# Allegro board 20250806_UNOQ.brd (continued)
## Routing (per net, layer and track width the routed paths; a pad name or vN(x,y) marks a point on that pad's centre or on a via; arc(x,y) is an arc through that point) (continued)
VBAT: length 0.4
  TOP w0.203: R603.2 45.73,16.34 45.73,16.05
  vias: v1(45.72,15.72) v1(45.72,15.46) v1(45.73,15.23) v1(45.97,15.72) v1(45.97,15.46) v1(45.98,15.23) v1(46.19,15.71) v1(46.18,15.46) v1(46.19,15.24) v1(46.43,15.71) v1(46.42,15.46) v1(46.43,15.24) v2(45.72,15.72) v2(45.72,15.46) v2(45.73,15.23) v2(45.97,15.72) v2(45.97,15.46) v2(45.98,15.23) v2(46.19,15.71) v2(46.18,15.46) v2(46.19,15.24) v2(46.43,15.71) v2(46.42,15.46) v2(46.43,15.24) v3(6.49,40.57) v3(6.49,40.12) v3(6.89,40.56) v3(6.89,40.11) v3(7.29,40.56) v3(7.29,40.11) v3(13.89,7.37) v3(14.17,7.06) v3(14.43,6.68) v3(14.86,6.68) v3(15.32,6.68) v3(15.57,7.14) v3(45.85,14.96) v3(46.22,14.96) v3(46.59,14.96) v3(46.74,15.66) v3(46.74,15.3) v3(46.94,14.99) v4(7.62,40.3) v4(7.62,40.04) v4(7.62,39.79) v4(7.87,40.3) v4(7.87,40.04) v4(7.87,39.79) v4(8.13,40.3) v4(8.13,40.04) v4(8.13,39.79) v4(14.4,7.54) v4(14.43,7.26) v4(14.58,7.01) v4(14.68,7.52) v4(14.68,7.26) v4(14.81,7.01) v4(14.94,7.52) v4(14.94,7.26) v4(15.04,7.01) v4(15.19,7.52) v4(15.19,7.26) v4(15.29,7.01) v5(7.4,14.04) v5(7.4,13.81) v5(7.4,13.56) v5(7.62,40.3) v5(7.62,40.04) v5(7.62,39.79) v5(7.62,14.04) v5(7.62,13.81) v5(7.62,13.56) v5(7.87,40.3) v5(7.87,40.04) v5(7.87,39.79) v5(7.85,14.04) v5(7.85,13.81) v5(7.85,13.56) v5(8.13,40.3) v5(8.13,40.04) v5(8.13,39.79) v5(8.11,14.04) v5(8.11,13.81) v5(8.11,13.56)
VBAT_CONN_VSNS_P: length 7.3
  S3 w0.064: v2(46.29,16.4) 46.29,16.47 46.36,16.54 46.53,16.54 46.61,16.46 46.61,16.23 46.52,16.14 45.11,16.14 43.82,14.85 v2(40.51,14.85)
VBUS_DIV8: length 4
  TOP w0.254: R3019.2 R3020.1 33.22,51.38 v2(33.06,51.55)
  G2 w0.203: v2(34.77,52.2) 34.82,52.25 34.92,52.25 v1(34.98,52.3)
  S3 w0.203: v3(32.94,51.16) 32.94,51.44 v2(33.06,51.55) ; v3(34.62,51.94) 34.62,52.04 v2(34.77,52.2)
  S6 w0.254: v3(32.94,51.16) 33.73,51.94 v3(34.62,51.94)
VBUS_POWER_SWITCH_DISABLE_N: length 47.9
  TOP w0.066: v2(44.34,50.31) 44.54,50.51 44.54,54.41 43.79,55.16 JCTL1.10
  S3 w0.064: v2(44.34,50.31) 44.34,48.12 v3(43.48,47.26) ; v3(19.97,37.5) 19.88,37.41 18.3,37.41 17.76,37.95 15.06,37.95 v3(13.8,39.21)
  S6 w0.064: v3(43.48,47.26) 43.48,47.21 41.58,45.31 41.58,44.95 39.29,42.66 37.46,42.66 36.58,41.78 34.65,41.78 33.25,40.39 22.15,40.39 19.97,38.21 v3(19.97,37.5) ; v3(13.8,39.21) 13.9,39.21 v4(14.05,39.07)
  G7 w0.064: v4(14.05,39.07) 13.61,38.63 12.79,38.63 v5(12.23,39.19)
AMUX_1_TP: length 6.5
  S3 w0.064: v2(39.66,8.85) 39.66,9.84 40.09,10.27 40.09,13.52 39.64,13.97 39.64,14.33 39.24,14.73 v2(39.24,14.81)
ANT_CH0: length 5.6
  TOP w0.066: U2901.2 19.36,62.95 18.89,63.42 15.88,63.42 15.71,63.59 ANT1.1
AUX_CTRL_1: length 13.1
  TOP w0.066: R3003.1 34.93,58.64 34.61,58.96 v2(34.2,58.96) ; U3001.G1 34.32,51.54 33.83,51.05 v2(33.83,50.23) R3001.1
  S3 w0.064: v2(33.83,50.23) 33.83,50.24 33.32,50.75 33.32,51.78 32.55,52.56 32.55,55.32 33.4,56.18 33.4,57.58 33.84,58.02 33.84,58.61 v2(34.2,58.96)
AUX_CTRL_2: length 15.6
  TOP w0.066: U3001.H1 34.57,50.86 34.54,50.83 R3002.1 34.52,49.86 v2(34.14,50.24) ; 36.79,57.5 36.79,57.03 36.49,56.74 35.08,56.74 34.37,57.45 34.37,58.16 v2(34.09,58.44)
  S3 w0.064: v2(34.09,58.44) 34.09,58.03 33.53,57.48 33.53,56.09 32.72,55.28 32.72,52.71 33.5,51.93 33.5,50.88 v2(34.14,50.24)
BAT_ID: length 8
  S3 w0.064: v2(38.89,8.86) 38.89,9.05 38.74,9.19 38.75,9.2 38.75,9.8 v2(38.93,9.99) 39.55,9.99 39.95,10.39 39.95,13.48 39.48,13.95 39.48,14.33 39.18,14.63 39.12,14.63 38.69,15.06 v2(38.69,15.41)
BAT_THERM: length 6.8
  S3 w0.064: v2(39.26,14.28) 39.26,13.97 39.8,13.43 39.8,10.52 39.52,10.24 38.74,10.24 v2(38.5,10) 38.63,9.87 38.63,9.25 38.4,9.02 v2(38.4,8.85)
BOOT_CAP: length 5.1
  TOP w0.15: v1(40.95,14.28) 40.96,14.27 41.36,14.27 41.65,13.98 43.32,13.98 v1(43.36,14.01)
  G2 w0.2: v1(40.95,14.28) 40.97,14.3 41.36,14.3 41.65,14.01 v1(43.36,14.01)
BOOT_CONFIG0: length 2.7
  TOP w0.066: SOC1.AH9 22.97,36.88 R1304.1 R1303.2
BOOT_CONFIG1: length 2.4
  TOP w0.066: SOC1.AJ7 23.73,38.12 22.88,38.12 R1306.1 R1305.2
BOOT_CONFIG2: length 2.9
  TOP w0.066: R1307.2 R1308.1 22.88,37.55 23.37,37.55 23.89,37.03 24.32,37.03 SOC1.AH8
BOOT_CONFIG3: length 2.9
  TOP w0.066: SOC1.AH6 24.1,38.08 23.5,38.68 22.86,38.68 R1310.1 R1309.2
CBLPWR_N: length 5.4
  TOP w0.066: PMIC1.T10 36.65,14.56 v2(36.65,14.55)
  S3 w0.064: v2(36.65,14.55) 36.65,14.18 36.25,13.78 36.25,12.34 36.1,12.19 36.1,11.4 36.19,11.31 36.19,10.45 36.2,10.44 36.33,10.3 36.56,10.3 v2(36.93,9.93)
CC_OUT: length 4.2
  S3 w0.064: v2(35.28,21.95) 35.74,21.95 35.84,21.84 35.84,18.45 35.86,18.43 v2(35.86,18.24)
CCI_I2C_SCL0: length 29.7
  S3 w0.064: v2(26.17,38.48) 25.62,37.93 19.91,37.93 19.57,37.59 18.4,37.59 17.85,38.14 16.53,38.14 12.68,41.99 12.68,48.01 13.76,49.09 13.76,51.18 13.96,51.38 v3(13.96,52.83)
  S6 w0.064: v5(15.7,53.05) 14.18,53.05 v3(13.96,52.83)
  BOTTOM w0.066: v5(15.7,53.05) 15.35,53.4 R2607.1
CCI_I2C_SCL0_CONN: length 2.5
  BOTTOM w0.066: JMEDIA1.51 13.34,54.17 13.79,53.72 D26051.2 R2607.2
CCI_I2C_SCL1: length 47.6
  S3 w0.064: v2(26.97,39.68) 26.97,39.8 25.7,41.07 22.86,41.07 20.75,43.18 18.85,43.18 16.38,45.65 16.38,51.28 14.4,53.26 14.4,58.43 v3(14.05,58.79)
  S6 w0.064: v3(14.05,58.79) 14.05,58.75 14.32,58.48 14.32,57.62 14.62,57.31 26.03,57.31 26.57,57.86 26.57,59.75 28.57,61.74 v5(29.06,61.74)
  BOTTOM w0.066: v5(29.06,61.74) 29.06,61.76 29.31,62 R2610.1 30.19,62 R2611.1
CCI_I2C_SCL1_CONN: length 3.3
  BOTTOM w0.066: R2611.2 30.77,61.93 D26049.2 30.77,60.66 31.11,60.31 JMEDIA1.24
CCI_I2C_SDA0: length 27.8
  S3 w0.064: v3(14.36,52.48) 14.18,52.3 14.18,51.34 13.96,51.12 13.96,49.02 12.84,47.9 12.84,42.13 16.64,38.33 17.93,38.33 18.52,37.74 19.47,37.74 19.83,38.1 25.62,38.1 25.94,38.42 25.94,38.65 v2(26.17,38.88)
  S6 w0.064: v3(14.36,52.48) 14.4,52.48 v5(14.76,52.83)
  BOTTOM w0.066: R2608.1 14.75,52.84 v5(14.76,52.83)
CCI_I2C_SDA0_CONN: length 3.3
  BOTTOM w0.066: R2608.2 12.92,52.84 12.51,53.25 D26050.2 12.51,53.86 12.06,54.3 12.06,54.95
CCI_I2C_SDA1: length 49.7
  S3 w0.064: v3(14,58.36) 14.22,58.13 14.22,53.19 16.21,51.21 16.21,45.57 18.75,43.03 19.75,43.03 19.76,43.02 20.71,43.02 22.83,40.89 25.65,40.89 26.77,39.78 26.77,39.09 v2(26.57,38.88)
  S6 w0.064: v3(14,58.36) 14.16,58.19 14.16,57.55 14.54,57.17 26.12,57.17 26.7,57.75 26.7,59.67 28.48,61.45 v5(28.7,61.45)
  BOTTOM w0.066: v5(28.7,61.45) 28.7,61.73 28.94,61.97 29.06,61.97 29.48,62.39 30.62,62.39 30.77,62.54 R2609.1 31.08,62.74 R2612.1
CCI_I2C_SDA1_CONN: length 3.6
  BOTTOM w0.066: 32.38,58.85 32.38,59.47 31.32,60.53 D26048.2 R2612.2
CDC_CP_FLY_N: length 2
  TOP w0.2: C501.2 42.19,19.59 41.52,18.91 PMIC1.A27 PMIC1.B26
CDC_CP_FLY_P: length 2.3
  TOP w0.2: C501.1 42.24,20.09 PMIC1.A25
CDC_CP_VNEG: length 2.9
  TOP w0.2: F501.1 43.95,19.25 C502.1 43.18,19.25 42.61,18.68 42.16,18.68 41.73,18.24 PMIC1.C27
CDC_PA_VNEG: length 4.7
  TOP w0.16: 41.23,17.4 40.82,17.4 40.67,17.25 PMIC1.K24 ; C503.1 42.49,18.23 41.65,17.39 PMIC1.F26
  TOP w0.2: 41.23,17.4 PMIC1.F26 ; F501.2 43.91,18.23 C503.1
CSI0_A0_CLK_M: length 25.4
  TOP w0.058: v2(30.66,39.69) 30.65,39.68 SOC1.N2
  S3 w0.053: v3(27.76,43.54) 27.58,43.36 27.58,42.95 28.12,42.42 29.6,42.42 30.8,41.22 30.8,40.37 30.9,40.27 30.9,39.93 v2(30.66,39.69)
  S6 w0.053: v3(27.76,43.54) 27.76,43.77 v5(27.69,43.85)
  BOTTOM w0.058: JMEDIA1.33 24.26,54.95 24.2,54.89 24.2,53.97 24.3,53.88 25.14,53.88 25.32,53.69 25.32,53.31 U2610.7 U2610.4 25.35,52.08 25.35,51.57 27.59,49.33 27.59,48.83 27.45,48.7 26.9,48.7 26.84,48.64 26.84,48.52 26.9,48.46 27.45,48.46 27.59,48.32 27.59,48.1 27.45,47.96 26.9,47.96 26.84,47.9 26.84,47.78 26.9,47.73 27.45,47.73 27.59,47.59 27.59,47.36 27.45,47.22 26.9,47.22 26.84,47.16 26.84,47.05 26.9,46.99 27.45,46.99 27.59,46.85 27.59,46.62 27.45,46.49 26.9,46.49 26.84,46.43 26.84,46.31 26.9,46.25 27.45,46.25 27.59,46.12 27.59,44.18 27.69,44.08 v5(27.69,43.85)
CSI0_A1_LN1_P: length 25.2
  TOP w0.058: 30.17,39.68 30.2,39.68 v2(30.27,39.61)
  S3 w0.05: 30.29,39.65 30.28,39.63
  S3 w0.053: v3(26.32,43.85) 26.5,43.67 26.5,43.47 27.94,42.04 29.39,42.04 30.31,41.11 30.31,39.74 30.29,39.72 30.29,39.65
  S3 w0.058: 30.28,39.63 30.27,39.62 v2(30.27,39.61)
  S6 w0.053: v5(26.39,44.13) 26.34,44.13 26.32,44.11 v3(26.32,43.85) ; v5(26.61,52.17) 26.72,52.07 26.72,51.7 26.66,51.65 26.24,51.65 26.19,51.7 26.19,51.79 26.14,51.84 26.03,51.84 25.98,51.79 25.98,51.7 25.92,51.65 25.82,51.65 25.76,51.7 25.76,51.79 25.71,51.84 25.6,51.84 25.55,51.79 25.55,51.7 25.5,51.65 25.17,51.65 24.99,51.47 24.99,50.94 v5(24.88,50.83)
  BOTTOM w0.058: v5(26.39,44.13) 26.48,44.22 26.48,45.18 24.98,46.68 24.98,47.24 24.92,47.3 24.58,47.3 24.44,47.43 24.44,47.66 24.58,47.8 24.92,47.8 24.98,47.86 24.98,47.97 24.92,48.03 24.58,48.03 24.44,48.17 24.44,48.4 24.58,48.53 24.92,48.53 24.98,48.59 24.98,48.71 24.92,48.77 24.58,48.77 24.44,48.91 24.44,49.13 24.58,49.27 24.92,49.27 24.98,49.33 24.98,50.73 v5(24.88,50.83) ; v5(26.61,52.17) 26.58,52.17 U2610.2 U2610.9 26.69,53.29 26.69,53.68 26.88,53.87 27.81,53.87 27.87,53.93 27.87,54.89 27.81,54.95 27.3,54.95
CSI0_A2_LN2_M: length 25.1
  S3 w0.05: 29.78,39.83 v2(29.78,39.68)
  S3 w0.053: 29.78,39.83 29.71,39.9 29.71,39.9 29.6,40.01 29.6,40.18 29.7,40.27 29.7,40.3 29.7,40.3 29.7,40.9 29.11,41.49 27.59,41.49 26.37,42.71 24.9,42.71 24.2,43.41 24.2,43.81 24.19,43.82 v3(24.02,43.82)
  S6 w0.053: v5(18.12,50.42) 18.23,50.53 18.61,50.53 19.2,51.12 19.2,52.05 v5(19.39,52.24) ; v5(24.11,44.1) 24.08,44.13 24.02,44.08 v3(24.02,43.82)
  BOTTOM w0.058: v5(19.39,52.24) U2609.10 19.2,53.31 19.2,53.62 19.32,53.74 20.25,53.74 20.39,53.88 20.39,54.89 20.45,54.95 JMEDIA1.39 ; v5(18.12,50.42) 18.22,50.52 18.65,50.52 24.21,44.96 24.21,44.19 v5(24.11,44.1)
CSI0_B0_LN0_P: length 25.4
  S3 w0.05: 31.07,40.44 31.07,40.43 31.08,40.43 31.08,39.8 30.85,39.58 30.85,39.21 30.78,39.14 30.71,39.14 v2(30.57,39.28)
  S3 w0.053: v3(28.35,43.54) 28.52,43.36 28.52,43.08 29.02,42.58 29.7,42.58 31.07,41.2 31.07,40.44
  S6 w0.053: v3(28.35,43.54) 28.35,43.79 28.4,43.85 v5(28.44,43.85)
  BOTTOM w0.058: JMEDIA1.23 31.62,54.95 31.68,54.89 31.68,53.92 31.86,53.74 32.7,53.74 32.81,53.63 32.81,53.29 U2606.6 U2606.5 32.63,51.96 32.8,51.79 32.8,51.11 32.45,50.76 32.36,50.76 32.32,50.8 32.24,50.8 32.16,50.72 32.16,50.63 32.2,50.59 32.2,50.51 31.9,50.21 31.82,50.21 31.52,50.5 31.33,50.5 31.17,50.34 31.17,50.14 31.46,49.85 31.46,49.77 31.38,49.69 31.29,49.69 31,49.98 30.81,49.98 30.65,49.82 30.65,49.62 30.94,49.33 30.94,49.25 30.86,49.17 30.77,49.17 30.48,49.46 30.29,49.46 30.13,49.3 30.13,49.1 30.42,48.81 30.42,48.73 30.34,48.65 30.25,48.65 29.96,48.94 29.77,48.94 29.6,48.77 29.6,48.58 29.9,48.29 29.9,48.21 28.54,46.85 28.54,44.18 28.44,44.08 v5(28.44,43.85)
CSI0_B1_LN1_M: length 25.1
  TOP w0.058: v2(30.22,39.2) 30.17,39.25 30.17,39.28
  S3 w0.05: 30.46,39.71 30.46,39.54 30.22,39.3 v2(30.22,39.2)
  S3 w0.053: v3(26.8,43.85) 26.62,43.67 26.62,43.52 27.99,42.15 29.44,42.15 30.43,41.16 30.43,39.74 30.46,39.71
  S6 w0.053: v5(25.21,50.83) 25.11,50.93 25.11,51.42 25.22,51.53 26.71,51.53 26.83,51.65 26.83,52.07 v5(26.94,52.17) ; v5(26.71,44.13) 26.75,44.16 26.8,44.11 v3(26.8,43.85)
  BOTTOM w0.058: v5(25.21,50.83) 25.11,50.73 25.11,49.27 24.97,49.14 24.63,49.14 24.57,49.08 24.57,48.96 24.63,48.9 24.97,48.9 25.11,48.77 25.11,48.54 24.97,48.4 24.63,48.4 24.57,48.34 24.57,48.22 24.63,48.17 24.97,48.17 25.11,48.03 25.11,47.8 24.97,47.66 24.63,47.66 24.57,47.6 24.57,47.49 24.63,47.43 24.97,47.43 25.11,47.29 25.11,46.74 26.62,45.23 26.62,44.22 v5(26.71,44.13) ; v5(26.94,52.17) U2610.1 U2610.10 26.82,53.31 26.82,53.62 26.94,53.74 27.87,53.74 28.01,53.88 28.01,54.89 28.07,54.95 JMEDIA1.27
CSI0_B2_LN3_P: length 25.3
  S3 w0.05: 29.97,40.44 29.97,40.43 29.97,40.43 29.97,39.49 v2(29.77,39.28)
  S3 w0.053: v3(25.18,43.84) 25.38,43.65 25.38,43.19 25.58,43 26.48,43 27.71,41.77 29.24,41.77 29.97,41.03 29.97,40.44
  S6 w0.053: v5(25.26,44.13) 25.26,43.92 v3(25.18,43.84)
  BOTTOM w0.058: JMEDIA1.47 16.38,54.95 16.44,54.89 16.44,53.92 16.62,53.74 17.46,53.74 17.57,53.63 17.57,53.29 U2609.6 U2609.5 17.39,51.98 17.57,51.8 17.57,51.49 17.8,51.27 19.14,51.27 24.81,45.6 24.81,45.52 24.78,45.49 24.78,45.41 24.86,45.33 24.95,45.33 24.97,45.35 25.06,45.35 25.36,45.05 25.36,44.76 25.3,44.7 25.21,44.7 25.15,44.64 25.15,44.53 25.21,44.47 25.3,44.47 25.36,44.41 25.36,44.23 v5(25.26,44.13)
CSI0_C0_LN0_M: length 25.3
  S3 w0.05: 31.19,40.44 31.19,40.43 31.19,40.43 31.19,39.76 30.97,39.54 30.97,39.16 30.83,39.03 30.71,39.03 v2(30.57,38.88)
  S3 w0.053: v3(28.82,43.54) 28.81,43.54 28.64,43.37 28.64,43.13 29.07,42.7 29.74,42.7 31.19,41.25 31.19,40.44
  S6 w0.053: v3(28.82,43.54) 28.82,43.79 v5(28.77,43.85)
  BOTTOM w0.058: v5(28.77,43.85) 28.77,44.08 28.67,44.18 28.67,46.79 30.03,48.15 30.03,48.34 29.74,48.64 29.74,48.72 29.82,48.8 29.9,48.8 30.2,48.51 30.39,48.51 30.55,48.67 30.55,48.87 30.26,49.16 30.26,49.24 30.34,49.32 30.43,49.32 30.72,49.03 30.91,49.03 31.07,49.19 31.07,49.39 30.78,49.68 30.78,49.76 30.86,49.84 30.95,49.84 31.24,49.55 31.43,49.55 31.59,49.71 31.59,49.91 31.3,50.2 31.3,50.28 31.39,50.37 31.47,50.37 31.76,50.07 31.95,50.07 32.94,51.06 32.94,51.8 33.13,51.99 U2606.4 U2606.7 32.94,53.31 32.94,53.69 32.76,53.88 31.91,53.88 31.82,53.97 31.82,54.89 31.88,54.95 32.38,54.95
CSI0_C1_LN2_P: length 25.1
  S3 w0.053: v2(29.78,40.08) 29.78,40.19 29.82,40.23 29.82,40.25 29.82,40.94 29.16,41.61 27.64,41.61 26.41,42.83 24.95,42.83 24.32,43.46 24.32,43.81 24.33,43.82 v3(24.5,43.82)
  S6 w0.053: v5(18.12,50.75) 18.22,50.65 18.56,50.65 18.73,50.81 18.73,50.89 18.66,50.96 18.66,51.03 18.74,51.11 18.81,51.11 18.88,51.04 18.95,51.04 19.08,51.17 19.08,51.55 19.03,51.6 18.95,51.6 18.9,51.66 18.9,51.76 18.95,51.82 19.03,51.82 19.08,51.87 19.08,52.05 v5(18.89,52.24) ; v5(24.44,44.1) 24.48,44.1 24.5,44.08 v3(24.5,43.82)
  BOTTOM w0.058: v5(24.44,44.1) 24.34,44.19 24.34,45.02 18.71,50.65 18.21,50.65 v5(18.12,50.75) ; 19.68,54.95 20.19,54.95 20.25,54.89 20.25,53.93 20.19,53.87 19.26,53.87 19.07,53.68 19.07,53.29 U2609.9 v5(18.89,52.24)
CSI0_C2_LN3_M: length 25.3
  S3 w0.05: v2(29.77,38.88) 30.02,39.13 30.02,39.37 30.09,39.44 30.09,40.43 30.09,40.43 30.09,40.44
  S3 w0.053: v3(25.66,43.84) 25.5,43.68 25.5,43.24 25.63,43.11 26.53,43.11 27.76,41.88 29.29,41.88 30.09,41.08 30.09,40.44
  S6 w0.053: v5(25.59,44.13) 25.59,43.91 v3(25.66,43.84)
  BOTTOM w0.058: v5(25.59,44.13) 25.49,44.23 25.49,45.11 19.2,51.4 17.86,51.4 17.71,51.55 17.71,51.79 17.89,51.97 U2609.4 U2609.7 17.7,53.31 17.7,53.69 17.52,53.88 16.68,53.88 16.58,53.97 16.58,54.89 16.64,54.95 17.14,54.95
CSI0_NC_CLK_P: length 25.5
  TOP w0.058: SOC1.N1 30.65,40.08 v2(30.66,40.09)
  S3 w0.053: v3(27.26,43.55) 27.31,43.55 27.47,43.39 27.47,43.28 27.43,43.24 27.34,43.24 27.32,43.21 27.32,43.08 27.34,43.05 27.43,43.05 27.45,43.02 27.45,42.92 28.07,42.3 29.56,42.3 30.68,41.18 30.68,40.11 v2(30.66,40.09)
  S6 w0.053: v3(27.26,43.55) 27.36,43.65 v5(27.36,43.85)
  BOTTOM w0.058: JMEDIA1.35 24,54.95 24.06,54.89 24.06,53.92 24.24,53.74 25.08,53.74 25.19,53.63 25.19,53.29 U2610.6 U2610.5 25.22,52.04 25.22,51.51 25.86,50.87 25.86,50.78 25.8,50.72 25.8,50.64 25.89,50.55 25.97,50.55 26.03,50.62 26.11,50.62 27.45,49.28 27.45,48.89 27.4,48.83 26.85,48.83 26.71,48.69 26.71,48.46 26.85,48.33 27.4,48.33 27.45,48.27 27.45,48.15 27.4,48.09 26.85,48.09 26.71,47.96 26.71,47.73 26.85,47.59 27.4,47.59 27.45,47.53 27.45,47.42 27.4,47.36 26.85,47.36 26.71,47.22 26.71,46.99 26.85,46.85 27.4,46.85 27.45,46.8 27.45,46.68 27.4,46.62 26.85,46.62 26.71,46.48 26.71,46.26 26.85,46.12 27.4,46.12 27.45,46.06 27.45,44.18 27.36,44.08 v5(27.36,43.85)
CSI1_A0_CLK_M: length 56.6
  TOP w0.058: SOC1.T2 29.12,39.93 29.12,39.93 29.06,39.99 v2(29.06,40.01)
  S3 w0.053: v2(29.06,40.01) 29.06,40.24 28.6,40.7 27.52,40.7 26.14,42.09 24.13,42.09 21.32,44.89 21.13,44.89 19.85,46.17 19.85,52.5 18.26,54.09 18.26,56.98 18.91,57.62 18.91,57.7 18.7,57.9 18.7,58.08 18.84,58.22 19.01,58.22 19.22,58.01 19.3,58.01 19.37,58.09 19.37,58.16 19.16,58.37 19.16,58.54 19.31,58.69 19.48,58.69 19.69,58.48 19.76,58.48 20.15,58.87 20.15,59.35 20.1,59.41 16.59,59.41 16.47,59.53 16.47,59.73 16.59,59.85 20.1,59.85 20.15,59.91 20.15,60.01 20.1,60.07 16.59,60.07 16.47,60.19 16.47,60.39 16.59,60.51 20.1,60.51 20.15,60.57 20.15,60.67 20.1,60.73 16.59,60.73 16.47,60.85 16.47,61.05 16.59,61.17 20.1,61.17 20.15,61.23 20.15,61.53 v3(19.96,61.72)
  S6 w0.053: v3(19.96,61.72) 20.13,61.89 20.13,62.02 v5(19.94,62.21)
  BOTTOM w0.058: v5(19.94,62.21) U2607.1 U2607.6 19.94,60.57 20.13,60.38 20.13,59.8 19.68,59.35 19.68,58.85
CSI1_A1_LN1_P: length 56.4
  S3 w0.051: 28.43,40.51 28.61,40.51 28.85,40.27 28.85,39.56 28.9,39.51 29.01,39.51 29.05,39.55 v2(29.05,39.65)
  S3 w0.053: v3(15.62,61.38) 15.44,61.2 15.44,61 15.49,60.95 15.54,60.95 15.59,60.9 15.59,60.79 15.54,60.74 15.49,60.74 15.44,60.68 15.44,60.39 15.96,59.87 15.96,58.97 16.17,58.76 17.53,58.76 17.67,58.62 17.67,58.41 17.55,58.29 16.13,58.29 16.09,58.25 16.09,58.12 16.13,58.08 17.64,58.08 17.75,57.97 17.75,57.74 17.63,57.62 16.11,57.62 16.06,57.57 16.06,57.46 16.11,57.41 17.63,57.41 17.75,57.29 17.75,57.08 17.63,56.96 16.11,56.96 16.06,56.91 16.06,56.8 16.11,56.75 17.63,56.75 17.75,56.63 17.75,56.42 17.63,56.3 16.11,56.3 16.06,56.25 16.06,56.14 16.11,56.09 17.63,56.09 17.75,55.97 17.75,55.76 17.63,55.64 16.11,55.64 16.06,55.59 16.06,55.48 16.11,55.43 17.63,55.43 17.75,55.31 17.75,55.1 17.63,54.98 16.11,54.98 16.06,54.93 16.06,54.82 16.11,54.77 17.45,54.77 17.57,54.65 17.57,54.44 17.45,54.32 16.11,54.32 16.06,54.27 16.06,54 18.03,52.03 18.03,47.33 20.8,44.56 21.3,44.56 23.91,41.95 26.09,41.95 27.53,40.51 28.43,40.51
  S6 w0.053: v3(15.62,61.38) v5(15.62,61.66)
  BOTTOM w0.058: 17.14,58.85 16.64,58.85 16.58,58.9 16.58,59.88 16.31,60.15 15.57,60.15 15.43,60.29 15.43,60.6 U2605.6 v5(15.62,61.66)
CSI1_A2_LN2_M: length 56.6
  S3 w0.053: v3(13.99,60.61) 14.18,60.42 14.18,60.23 15.3,59.11 15.3,53.8 17.42,51.68 17.42,46.88 20.33,43.97 21.06,43.97 23.47,41.56 25.9,41.56 27.57,39.89 28.36,39.89 v2(28.5,39.75)
  S6 w0.053: v5(25.05,62.35) 25.18,62.48 25.18,62.65 25.02,62.81 24.26,62.81 24.01,62.56 24.01,62.45 24.75,61.7 24.75,61.52 24.61,61.38 24.44,61.38 23.64,62.18 23.56,62.18 23.48,62.11 23.48,62.04 24.29,61.24 24.29,61.06 24.14,60.91 23.98,60.91 23.17,61.72 23.09,61.72 23.01,61.64 23.01,61.57 23.82,60.77 23.82,60.59 23.67,60.44 23.51,60.44 22.71,61.25 22.62,61.25 22.55,61.17 22.55,61.11 23.35,60.3 23.35,60.12 23.21,59.98 23.04,59.98 22.35,60.67 22.28,60.67 21.61,60 14.43,60 14.17,60.26 14.17,60.43 v3(13.99,60.61)
  BOTTOM w0.058: U2608.1 v5(25.05,62.35) U2608.10 25.05,61.44 25.24,61.25 25.24,61.13 24.06,59.95 24.06,58.9 24,58.85 JMEDIA1.36
CSI1_B0_LN0_P: length 56.5
  S3 w0.05: 29.39,39.3 v2(29.37,39.28)
  S3 w0.053: v3(14.12,61.34) 13.94,61.52 13.94,61.93 14.26,62.25 14.59,62.25 14.64,62.2 14.64,62.1 14.69,62.05 14.8,62.05 14.85,62.1 14.85,62.2 14.91,62.25 15.01,62.25 15.07,62.2 15.07,62.1 15.12,62.05 15.23,62.05 15.28,62.1 15.28,62.2 15.33,62.25 15.44,62.25 15.49,62.2 15.49,62.1 15.55,62.05 15.65,62.05 15.71,62.1 15.71,62.2 15.76,62.25 20.55,62.25 20.67,62.37 20.67,62.95 20.72,63.01 20.83,63.01 20.88,62.95 20.88,62.37 21,62.25 21.21,62.25 21.33,62.37 21.33,62.95 21.38,63.01 21.49,63.01 21.54,62.95 21.54,62.37 21.66,62.25 21.87,62.25 21.99,62.37 21.99,62.95 22.04,63.01 22.15,63.01 22.2,62.95 22.2,62.37 22.32,62.25 22.6,62.25 22.7,62.15 22.7,61.79 22.65,61.74 21.41,61.74 21.3,61.63 21.3,61.42 21.43,61.29 22.65,61.29 22.7,61.24 22.7,61.13 22.65,61.08 21.12,61.08 21,60.96 21,60.75 21.12,60.63 22.07,60.63 22.13,60.58 22.13,60.47 22.07,60.42 21.12,60.42 21,60.3 21,60.09 21.12,59.97 21.74,59.97 21.79,59.92 21.79,59.64 18.91,56.76 18.91,54.21 20.36,52.76 20.36,46.31 21.32,45.35 21.51,45.35 24.47,42.39 26.24,42.39 27.41,41.22 28.94,41.22 29.46,40.71 29.46,40.38 29.37,40.3 29.37,39.36 29.39,39.35 29.39,39.3
  S6 w0.053: v3(14.12,61.34) v5(14.12,61.66)
  BOTTOM w0.058: v5(14.12,61.66) U2605.9 13.94,60.6 13.94,60.22 13.72,60 12.9,60 12.77,59.87 12.77,58.9 12.83,58.85 JMEDIA1.52
CSI1_B1_LN1_M: length 56.5
  S3 w0.051: 28.43,40.39 28.57,40.39 28.74,40.22 28.74,39.51 28.85,39.4 29,39.4 29.05,39.35 v2(29.05,39.25)
  S3 w0.053: 28.43,40.39 27.48,40.39 26.04,41.83 23.86,41.83 21.25,44.44 20.75,44.44 17.91,47.28 17.91,51.98 15.94,53.95 15.94,54.32 16.06,54.44 17.4,54.44 17.45,54.49 17.45,54.6 17.4,54.65 16.06,54.65 15.94,54.77 15.94,54.98 16.06,55.1 17.58,55.1 17.63,55.15 17.63,55.26 17.58,55.31 16.06,55.31 15.94,55.43 15.94,55.64 16.06,55.76 17.58,55.76 17.63,55.81 17.63,55.92 17.58,55.97 16.06,55.97 15.94,56.09 15.94,56.3 16.06,56.42 17.58,56.42 17.63,56.47 17.63,56.58 17.58,56.63 16.06,56.63 15.94,56.75 15.94,56.96 16.06,57.08 17.58,57.08 17.63,57.13 17.63,57.24 17.58,57.29 16.06,57.29 15.94,57.41 15.94,57.62 16.06,57.74 17.58,57.74 17.63,57.79 17.63,57.92 17.59,57.96 16.08,57.96 15.97,58.07 15.97,58.3 16.09,58.41 17.5,58.41 17.55,58.46 17.55,58.58 17.48,58.64 16.12,58.64 15.84,58.92 15.84,59.82 15.32,60.34 15.32,61.2 v3(15.14,61.38)
  S6 w0.053: v3(15.14,61.38) 15.14,61.63 v5(15.12,61.66)
  BOTTOM w0.058: v5(15.12,61.66) U2605.7 15.3,60.6 15.3,60.23 15.51,60.02 16.25,60.02 16.44,59.83 16.44,58.9 16.38,58.85 JMEDIA1.48
CSI1_B2_LN3_P: length 56.8
  S3 w0.053: v2(28.57,39.28) 28.43,39.14 28.12,39.14 25.86,41.4 23.16,41.4 21.04,43.53 20.09,43.53 16.96,46.66 16.96,51.49 14.91,53.54 14.91,58.85 13.43,60.33 13.03,60.33 v3(12.86,60.51)
  S6 w0.053: v3(12.86,60.51) 13.04,60.33 13.43,60.33 15.09,58.66 15.09,58.07 15.36,57.8 25.21,57.8 25.62,58.21 25.62,59.71 26.61,60.7 26.61,60.77 26.59,60.79 26.59,60.87 26.67,60.95 26.74,60.95 26.76,60.92 26.84,60.92 26.91,61 26.91,61.07 26.89,61.1 26.89,61.17 26.97,61.25 27.04,61.25 27.06,61.23 27.14,61.23 27.52,61.61 27.52,61.7 27.47,61.75 27.38,61.75 27.33,61.81 27.33,61.91 27.38,61.97 27.47,61.97 27.52,62.02 27.52,62.63 27.35,62.81 26.91,62.81 26.86,62.75 26.86,62.56 27.05,62.37 v5(27.05,62.34)
  BOTTOM w0.058: JMEDIA1.28 28.07,58.85 28.01,58.9 28.01,59.94 26.86,61.09 26.86,61.26 27.05,61.45 U2608.6 v5(27.05,62.34) U2608.5
CSI1_C0_LN0_M: length 56.6
  S3 w0.05: 29.54,39.21 29.54,39.06 v2(29.37,38.88)
  S3 w0.053: 29.54,39.21 29.54,39.21 29.54,39.36 29.49,39.41 29.49,40.25 29.57,40.34 29.57,40.76 28.99,41.34 27.45,41.34 26.29,42.51 24.52,42.51 21.56,45.47 21.37,45.47 20.48,46.36 20.48,52.81 19.03,54.26 19.03,56.71 21.91,59.59 21.91,59.97 21.79,60.09 21.17,60.09 21.12,60.14 21.12,60.25 21.17,60.3 22.12,60.3 22.25,60.42 22.25,60.63 22.12,60.75 21.17,60.75 21.12,60.8 21.12,60.91 21.17,60.96 22.7,60.96 22.82,61.08 22.82,61.29 22.7,61.41 21.48,61.41 21.42,61.47 21.42,61.58 21.46,61.62 22.7,61.62 22.82,61.74 22.82,62.2 22.65,62.37 22.37,62.37 22.32,62.42 22.32,63 22.2,63.12 21.99,63.12 21.87,63 21.87,62.42 21.82,62.37 21.71,62.37 21.66,62.42 21.66,63 21.54,63.12 21.33,63.12 21.21,63 21.21,62.42 21.16,62.37 21.05,62.37 21,62.42 21,63 20.88,63.12 20.67,63.12 20.55,63 20.55,62.42 20.5,62.37 14.21,62.37 13.82,61.98 13.82,61.52 v3(13.64,61.34)
  S6 w0.053: v3(13.64,61.34) 13.64,61.63 v5(13.62,61.66)
  BOTTOM w0.058: 12.06,58.85 12.57,58.85 12.63,58.9 12.63,59.92 12.84,60.13 13.66,60.13 13.81,60.28 13.81,60.6 U2605.10 v5(13.62,61.66)
CSI1_C1_LN2_P: length 56.6
  S3 w0.053: v2(28.5,40.15) 28.36,40.01 27.62,40.01 25.95,41.68 23.52,41.68 21.11,44.09 20.38,44.09 17.54,46.93 17.54,51.73 15.42,53.85 15.42,59.16 14.3,60.28 14.3,60.44 v3(14.47,60.61)
  S6 w0.053: v3(14.47,60.61) 14.29,60.43 14.29,60.31 14.48,60.12 21.56,60.12 22.23,60.78 22.4,60.78 23.09,60.09 23.16,60.09 23.23,60.17 23.23,60.25 22.43,61.06 22.43,61.22 22.57,61.37 22.75,61.37 23.56,60.56 23.63,60.56 23.7,60.64 23.7,60.72 22.9,61.53 22.9,61.69 23.04,61.83 23.22,61.83 24.03,61.03 24.09,61.03 24.17,61.1 24.17,61.19 23.36,61.99 23.36,62.16 23.51,62.3 23.69,62.3 24.49,61.5 24.56,61.5 24.64,61.57 24.64,61.65 23.89,62.4 23.89,62.61 24.22,62.93 24.58,62.93 24.68,63.03 24.79,63.03 24.89,62.93 25.07,62.93 25.3,62.7 25.3,62.45 25.4,62.35 v5(25.55,62.35)
  BOTTOM w0.058: JMEDIA1.34 24.26,58.85 24.2,58.9 24.2,59.9 25.37,61.07 25.37,61.27 25.55,61.45 U2608.9 v5(25.55,62.35) U2608.2
CSI1_C2_LN3_M: length 56.8
  S3 w0.053: v2(28.57,38.88) 28.43,39.02 28.42,39.02 28.07,39.02 25.81,41.29 23.12,41.29 20.99,43.41 20.04,43.41 16.84,46.61 16.84,51.44 14.79,53.49 14.79,58.81 13.38,60.22 13.04,60.22 v3(12.86,60.03)
  S6 w0.053: v5(26.55,62.34) 26.74,62.53 26.74,62.8 26.86,62.92 27.4,62.92 27.64,62.68 27.64,61.56 25.74,59.66 25.74,58.16 25.26,57.68 15.31,57.68 14.97,58.02 14.97,58.62 13.38,60.21 13.03,60.21 v3(12.86,60.03)
  BOTTOM w0.058: U2608.4 v5(26.55,62.34) U2608.7 26.55,61.47 26.73,61.29 26.73,61.03 27.87,59.89 27.87,58.9 27.81,58.85 27.3,58.85
CSI1_NC_CLK_P: length 56.6
  TOP w0.058: SOC1.T1 29.23,40.22 v2(29.23,40.48)
  S3 w0.053: v2(29.23,40.48) 29.23,40.43 29.16,40.36 29.1,40.36 28.96,40.5 28.96,40.61 28.86,40.71 28.76,40.71 28.65,40.82 27.57,40.82 26.18,42.2 24.17,42.2 21.37,45.01 21.18,45.01 19.97,46.22 19.97,52.55 18.38,54.14 18.38,56.93 19.02,57.57 19.02,57.74 18.81,57.95 18.81,58.03 18.89,58.1 18.96,58.1 19.17,57.9 19.35,57.9 19.49,58.04 19.49,58.21 19.28,58.42 19.28,58.5 19.36,58.57 19.43,58.57 19.64,58.36 19.81,58.36 20.27,58.82 20.27,59.4 20.15,59.52 16.64,59.52 16.59,59.58 16.59,59.68 16.64,59.74 20.15,59.74 20.27,59.86 20.27,60.06 20.15,60.18 16.64,60.18 16.59,60.24 16.59,60.34 16.64,60.4 20.15,60.4 20.27,60.52 20.27,60.72 20.15,60.84 16.64,60.84 16.59,60.9 16.59,61 16.64,61.06 20.15,61.06 20.27,61.18 20.27,61.55 v3(20.44,61.72)
  S6 w0.053: v3(20.44,61.72) 20.25,61.91 20.25,62.02 v5(20.44,62.21)
  BOTTOM w0.058: v5(20.44,62.21) U2607.2 U2607.5 20.44,60.53 20.26,60.35 20.26,59.84 20.95,59.15 JMEDIA1.40
DC_IN: length 4.3
  V5 w0.203: 2.54,21.81 JANALOG1.8 ; JANALOG1.8 2.54,23.91 ; JANALOG1.8 3.59,22.86 ; JANALOG1.8 1.49,22.86
  S6 w0.5: 7.12,54.93 v5(7.06,54.99)
  vias: v3(1.67,45.51) v3(1.84,45.14) v3(2.07,45.52) v3(2.25,45.15) v3(6.52,55.24) v3(6.52,54.85) v3(6.85,54.39) v3(6.89,55.55) v3(7.29,55.54) v3(7.27,54.39) v4(2.55,45.38) v4(2.55,45.13) v4(2.79,45.38) v4(2.79,45.13) v4(3.04,45.38) v4(3.04,45.13) v4(3.28,45.38) v4(3.28,45.13) v4(6.82,55.26) v4(6.82,55) v4(6.82,54.72) v4(7.06,55.25) v4(7.06,54.71) v4(7.3,55.25) v4(7.3,54.99) v4(7.3,54.71) v5(2.55,45.38) v5(2.55,45.13) v5(2.79,45.38) v5(2.79,45.13) v5(3.04,45.38) v5(3.04,45.13) v5(3.28,45.38) v5(3.28,45.13) v5(6.82,55.26) v5(6.82,55) v5(6.82,54.72) v5(7.06,55.25) v5(7.06,54.71) v5(7.3,55.25) v5(7.3,54.99) v5(7.3,54.71)
DDR_RESET_N: length 17.1
  TOP w0.066: DRAM1.T11 45.86,31.36 45.97,31.24 45.97,28.04 45.72,27.79 40.33,27.79 v2(40.28,27.84)
  S3 w0.079: v2(34.17,30.08) 34.66,30.08 34.98,29.77 35.38,29.77 36.17,28.98 36.17,28.39 36.19,28.37 36.19,28.35 36.91,27.64 38.95,27.64 39.15,27.84 v2(40.28,27.84)
DRAM_ZQ0: length 0.6
  S3 w0.2: v3(40.65,41.43) v5(40.65,41.11)
  S6 w0.2: v5(40.65,41.11) v3(40.65,41.43)
DRAM_ZQ1: length 0.8
  S3 w0.2: v2(43.06,41.11) v3(43.06,41.39)
  S6 w0.2: v5(43.06,41.95) v3(43.06,41.39)
DSI0_REXT_PLL: length 2.1
  TOP w0.05: 31.37,28.33 31.37,28.48 SOC1.L30
  TOP w0.066: R1522.1 30.79,27.34 31.37,27.92 31.37,28.33
DSI1_CLK_M_TP: length 5.5
  S3 w0.05: v2(30.97,29.68) 31.11,29.54
  S3 w0.053: 31.11,29.54 31.23,29.54 31.29,29.47 31.33,29.47 31.6,29.2 31.6,28.96 31.59,28.96 31.59,28.81 31.6,28.8 31.6,28.35 31.6,28.35 31.6,26.55 30.66,25.61 30.27,25.61 30.14,25.48 v2(30.14,25.41)
DSI1_CLK_P_TP: length 5.5
  S3 w0.05: v2(30.97,29.28) 31.11,29.42 31.11,29.42
  S3 w0.053: v2(30.14,25.95) 30.14,25.85 30.27,25.73 30.61,25.73 30.76,25.88 30.76,25.95 30.73,25.98 30.73,26.06 30.8,26.13 30.88,26.13 30.91,26.1 30.98,26.1 31.06,26.18 31.06,26.25 31.03,26.28 31.03,26.36 31.1,26.43 31.18,26.43 31.21,26.4 31.29,26.4 31.48,26.6 31.48,28.3 31.48,28.3 31.48,28.75 31.47,28.76 31.47,29 31.48,29.01 31.48,29.16 31.28,29.36 31.24,29.36 31.18,29.42 31.11,29.42
EAR_M: length 3.6
  S3 w0.15: v2(44.88,18.14) 42.88,18.14 42.42,17.68 v2(41.52,17.68)
EAR_M_R: length 26.8
  TOP w0.2: v2(45.92,18.14) 45.91,18.14 R2671.2
  S3 w0.2: v3(46.36,18.22) 46,18.22 v2(45.92,18.14)
  S6 w0.2: v3(46.36,18.22) 46.69,18.22 v5(46.76,18.29)
  BOTTOM w0.203: v5(46.76,18.29) 46.78,18.31 47.06,18.31 47.36,18.01 47.36,16.2 44.87,13.71 38.19,13.71 37.65,14.25 29.99,14.25 29.54,14.25 28.95,14.25 28.6,13.9 28.18,13.9 D26064.2
  BOTTOM w0.254: 27.3,11.98 27.3,12.67 27.81,13.18 D26064.2
EAR_P: length 3.8
  S3 w0.15: v2(44.86,18.68) 44.84,18.66 42.97,18.66 42.27,17.96 v2(41.35,17.96)
EAR_P_R: length 26.7
  TOP w0.254: R2670.2 45.91,18.68 v2(45.92,18.67)
  S3 w0.2: v3(46.36,18.7) 46.32,18.67 v2(45.92,18.67)
  S6 w0.2: v3(46.36,18.7) 46.69,18.7 46.76,18.63 v5(46.76,18.62)
  BOTTOM w0.203: v5(46.76,18.62) 46.78,18.6 47.18,18.6 47.65,18.13 47.65,16.08 44.99,13.42 38.07,13.42 37.53,13.96 29.07,13.96 28.83,13.72 D26063.2
  BOTTOM w0.254: 28.57,11.98 28.57,13.22 28.83,13.47 D26063.2
EBI0_CA_0: length 6.1
  TOP w0.084: v2(38.67,36.23) 38.67,36.48 38.6,36.56 38.26,36.56 DRAM1.H2
  S3 w0.079: v2(34.17,36.85) 35.81,36.85 35.91,36.75 35.91,36.12 36.16,35.86 37.78,35.86 38.15,36.23 v2(38.67,36.23)
EBI0_CA_1: length 6.2
  TOP w0.066: 35.74,36.73 35.22,36.73 SOC1.B10
  TOP w0.084: 35.74,36.73 36.12,36.35 36.32,36.35 36.42,36.45 36.42,36.62 36.61,36.82 36.89,36.82 37.04,36.67 37.04,36.45 36.86,36.27 36.7,36.27 36.54,36.12 36.54,35.93 36.83,35.64 37.02,35.64 37.09,35.7 37.09,36.08 37.26,36.26 37.58,36.26 37.93,35.91 DRAM1.J2
EBI0_CA_2: length 9.5
  TOP w0.084: v2(41.13,37.51) 40.93,37.51 40.93,37.52 38.13,37.52 37.74,37.91 37.74,37.97 37.58,38.14 37.35,38.14 36.96,37.75 36.59,37.75 36.23,37.39 35.74,37.39 35.63,37.28 SOC1.A8 ; v2(42.72,37.03) 42.72,37.03 42.84,36.91 43.51,36.91 43.86,36.56 DRAM1.H9
  S3 w0.079: v2(41.13,37.51) 42.23,37.51 42.53,37.22 v2(42.72,37.03)
EBI0_CA_3: length 10.8
  TOP w0.066: 35.71,37.13 35.62,37.05 35.2,37.05 34.97,37.28 SOC1.B8
  TOP w0.084: DRAM1.H10 44.35,36.24 42.97,36.24 42.95,36.27 42.94,36.27 42.83,36.38 42.83,36.38 v2(42.7,36.52) ; 35.71,37.13 36.35,37.13 36.72,37.5 37.89,37.5 37.98,37.41 37.98,37.09 38.18,36.88 40.84,36.88 v2(41.1,36.63)
  S3 w0.079: v2(42.7,36.52) 41.21,36.52 v2(41.1,36.63)
EBI0_CA_4: length 12.8
  TOP w0.066: SOC1.B9 35.89,36.88
  TOP w0.084: v2(42.63,36.05) 42.63,35.76 42.84,35.55 44.82,35.55 45.01,35.74 45.01,36.1 45.46,36.56 DRAM1.H11 ; v2(41.35,36.21) 39.54,36.21 39.35,36.03 39.35,35.75 39.22,35.61 38.89,35.61 38.7,35.8 38.7,35.88 38.31,36.27 38.08,36.27 37.82,36.53 37.82,36.66 37.56,36.91 37.18,36.91 36.99,37.1 36.64,37.1 36.42,36.88 35.89,36.88
  S3 w0.079: v2(41.35,36.21) 42.2,36.21 42.37,36.05 v2(42.63,36.05)
EBI0_CA_5: length 13.9
  TOP w0.084: DRAM1.J11 45.46,35.9 45.65,35.9 45.87,36.12 45.87,36.66 45.64,36.88 44.15,36.88 44.15,36.88 v2(43.99,36.88)
  S3 w0.06: v2(33.77,37.68) 33.78,37.68 33.98,37.88 34.49,37.88
  S3 w0.079: v2(43.99,36.88) 43.51,36.88 43.49,36.9 42.95,36.9 42.82,36.77 41.46,36.77 40.67,37.57 39.07,37.57 38.94,37.69 37.87,37.69 37.74,37.57 37.18,37.57 36.86,37.88 34.49,37.88
EBI0_CAL: length 1.2
  S3 w0.064: v3(33.69,34.88) 33.68,34.88 v2(33.37,34.88)
  S6 w0.064: v3(33.69,34.88) 34.28,34.88 v5(34.39,34.77)
  BOTTOM w0.066: R1401.2 v5(34.39,34.77)
EBI0_CKE_0: length 6.9
  S3 w0.076: v2(33.77,37.28) 33.97,37.48 34.5,37.48
  S3 w0.079: 34.5,37.48 36.39,37.48 36.7,37.17 37.9,37.17 38.19,36.88 39.11,36.88 39.39,36.6 39.39,36.45 v2(39.86,35.97)
EBI0_CKE_1: length 8.3
  S3 w0.076: 34.3,37.06 33.95,37.06 v2(33.77,36.88)
  S3 w0.079: v2(40.66,35.91) 40.47,35.72 39.76,35.72 39.27,36.21 39.05,36.21 38.78,36.48 37.99,36.48 37.59,36.08 36.35,36.08 36.16,36.27 36.16,36.94 36.05,37.06 34.3,37.06
EBI0_CLK_M: length 11.3
  TOP w0.053: v2(43.69,35.92) 43.7,35.91 DRAM1.J9
  S3 w0.051: 34.41,36.31 34.39,36.29 34.09,36.29 33.89,36.48 v2(33.77,36.48)
  S3 w0.053: 34.41,36.31 35.18,36.31 36.52,34.96 40.21,34.96 40.23,34.98 40.24,34.98 40.74,35.48 43.34,35.48 43.53,35.67 43.53,35.86 43.59,35.92 v2(43.69,35.92)
EBI0_CLK_P: length 10.9
  S3 w0.051: v2(34.17,36.48) 34.23,36.42
  S3 w0.053: v2(43.22,35.91) 43.22,35.91 43.22,36.11 43.26,36.14 43.36,36.14 43.41,36.09 43.41,35.72 43.3,35.6 40.69,35.6 40.17,35.08 36.57,35.08 35.23,36.42 34.23,36.42
EBI0_CS_0: length 6.4
  S3 w0.076: 34.64,37.68 v2(34.17,37.68)
  S3 w0.079: v2(39.88,36.43) 39.69,36.43 39.59,36.54 39.59,36.66 38.7,37.54 38.13,37.54 37.99,37.4 36.88,37.4 36.6,37.68 34.64,37.68
EBI0_CS_1: length 6
  S3 w0.076: 37.47,36.28 36.74,36.28 ; v2(34.17,37.27) 34.58,37.27 34.58,37.27
  S3 w0.079: 34.58,37.27 36.29,37.27 36.45,37.1 36.45,36.4 36.58,36.28 36.74,36.28 ; v2(39.13,36.49) 38.94,36.68 37.87,36.68 37.47,36.28
EBI0_DMI_0: length 5.4
  S3 w0.076: 34.32,38.48 v2(34.17,38.48)
  S3 w0.079: v2(39.06,39.8) 38.6,39.8 37.7,38.9 36.84,38.9 36.46,38.51 36.42,38.48 34.32,38.48
EBI0_DMI_1: length 15.1
  TOP w0.084: SOC1.A11 35.72,36.08 37,34.8 40.84,34.8 41.09,35.05 41.09,35.3 41.17,35.39 41.23,35.39 41.32,35.3 41.32,35.13 41.38,35.07 41.54,35.07 41.6,35.13 41.6,35.48 41.78,35.66 41.78,39.03 41.84,39.09 41.96,39.09 42.07,38.99 42.18,38.99 42.24,39.04 42.24,39.17 42.11,39.3 42.11,39.42 42.21,39.52 42.43,39.52 42.43,39.52 44.12,39.52 44.41,39.81 44.66,39.81
EBI0_DQ0: length 5.5
  TOP w0.084: SOC1.A5 36.48,39.59 36.48,39.79 36.48,39.8 36.48,40.76 37.18,41.45 37.73,41.45 37.88,41.3 37.88,40.84 DRAM1.B2
EBI0_DQ1: length 5.5
  TOP w0.051: 35.49,38.24 35.21,38.24 34.97,38.48 SOC1.B5
  TOP w0.084: 35.49,38.24 36.69,39.44 36.69,40.39 37.04,40.75 37.58,40.75 37.98,40.35 37.98,40.1 38.26,39.81
EBI0_DQ2: length 6.2
  TOP w0.051: 35.65,38.08 35.65,38.08 SOC1.B6
  TOP w0.084: 35.65,38.08 36.61,39.04 36.98,39.41 36.98,40 37.13,40.16 37.64,40.16 37.82,39.98 37.82,39.73 38.03,39.52 38.36,39.52 38.55,39.33 38.55,38.8 DRAM1.E2
EBI0_DQ3: length 4.2
  TOP w0.084: SOC1.A7 35.97,37.68 36.42,38.13 36.8,38.13 36.91,38.23 36.91,38.62 37.13,38.84 37.55,38.84 37.77,38.62 37.77,38.29 38.2,37.86 DRAM1.F2
EBI0_DQ4: length 9.8
  S3 w0.076: 34.39,39.1 34.37,39.1 v2(34.17,38.9)
  S3 w0.079: 34.39,39.1 35.88,39.1 37.71,40.94 39.11,40.94 39.14,40.97 39.4,40.97 39.58,40.79 39.85,40.79 40.11,40.54 40.11,38.76 39.86,38.51 v2(39.86,37.85)
EBI0_DQ5: length 7
  TOP w0.08: 35.49,37.93 35.21,37.93 34.97,37.68 SOC1.B7
  TOP w0.084: DRAM1.E4 39.53,38.18 38.18,38.18 37.98,38.38 37.98,39.2 37.69,39.49 37.21,39.49 37.15,39.42 37.15,39.17 36.9,38.92 35.97,37.99 35.91,37.93 35.49,37.93
EBI0_DQ6: length 6.8
  S3 w0.06: 34.67,38.68 33.97,38.68 v2(33.77,38.48)
  S3 w0.079: 34.67,38.68 36.35,38.68 36.37,38.71 37.34,39.67 37.53,39.67 37.53,39.68 37.79,39.68 37.8,39.67 37.97,39.67 38.33,40.03 39.63,40.03 v2(39.86,39.8)
EBI0_DQ7: length 6.3
  S3 w0.079: v2(39.86,40.45) 39.66,40.25 38.72,40.25 38.31,40.66 37.76,40.66 35.98,38.88 v2(34.57,38.88)
EBI0_DQ8: length 17.7
  S3 w0.076: 34.06,34.99 v2(33.77,35.28)
  S3 w0.079: v2(45.46,40.45) 45.74,40.18 45.74,36.39 43.67,34.33 41.22,34.33 41.2,34.3 41.18,34.3 40.8,33.93 35.87,33.93 34.8,34.99 34.06,34.99
EBI0_DQ9: length 16.4
  S3 w0.076: v2(34.17,35.24) 34.62,35.24
  S3 w0.079: 34.62,35.24 34.87,35.24 36,34.11 40.76,34.11 41.16,34.51 43.56,34.51 45.51,36.47 45.51,38.09 45.1,38.5 45.1,39.44 v2(45.46,39.81)
EBI0_DQ10: length 17.1
  TOP w0.08: SOC1.B13 34.97,35.28 35.21,35.52 35.48,35.52 35.63,35.38
  TOP w0.084: DRAM1.E11 45.63,38.34 45.75,38.34 45.94,38.15 46.5,38.15 46.63,38.02 46.63,34.69 46.24,34.3 36.71,34.3 35.63,35.38
EBI0_DQ11: length 15.2
  TOP w0.08: 35.63,35.84 35.21,35.84 SOC1.B11
  TOP w0.084: 35.63,35.84 35.68,35.84 36.88,34.63 41.49,34.63 41.99,35.14 41.99,38.45 42.37,38.82 43.19,38.82 43.58,38.43 43.58,38.39 43.78,38.18 45.14,38.18 DRAM1.F11
EBI0_DQ12: length 15.1
  TOP w0.08: 35.63,35.63 35.59,35.68 SOC1.B12
  TOP w0.084: 35.63,35.63 36.8,34.47 42.08,34.47 42.4,34.78 42.4,35.11 42.34,35.16 42.23,35.16 42.17,35.22 42.17,35.29 42.23,35.35 42.34,35.35 42.4,35.4 42.4,35.48 42.34,35.53 42.23,35.53 42.17,35.58 42.17,35.66 42.23,35.71 42.34,35.71 42.4,35.77 42.4,35.84 42.34,35.9 42.23,35.9 42.17,35.95 42.17,36.03 42.23,36.08 42.34,36.08 42.4,36.14 42.4,36.21 42.34,36.27 42.23,36.27 42.17,36.32 42.17,36.4 42.23,36.45 42.34,36.45 42.4,36.5 42.4,36.58 42.34,36.63 42.23,36.63 42.17,36.69 42.17,36.76 42.23,36.82 42.34,36.82 42.4,36.87 42.4,36.95 42.34,37 42.23,37 42.17,37.05 42.17,37.13 42.23,37.18 42.34,37.18 42.4,37.24 42.4,37.31 42.34,37.37 42.23,37.37 42.17,37.42 42.17,37.5 42.23,37.55 42.34,37.55 42.4,37.61 42.4,37.89 42.69,38.18 43.16,38.18 43.35,37.99 43.73,37.99 DRAM1.F9
EBI0_DQ13: length 17.4
  TOP w0.08: SOC1.A10 35.66,36.48 36.72,35.42
  TOP w0.084: DRAM1.E9 44.15,38.8 44.15,39.05 44.58,39.48 44.84,39.48 45.1,39.75 45.1,39.9 44.87,40.13 42.44,40.13 41.68,40.13 41.58,40.03 41.58,36.12 41.03,35.58 39.55,35.58 39.35,35.38 39.35,35.14 39.18,34.97 38.94,34.97 38.78,35.14 38.78,35.38 38.58,35.58 37.38,35.58 37.22,35.42 36.72,35.42
EBI0_DQ14: length 16.2
  S3 w0.06: 34.41,35.88 33.97,35.88 v2(33.77,36.08)
  S3 w0.079: v2(43.86,39.81) 44.15,39.53 44.15,39.03 44.15,39.03 44.15,38.02 44.93,37.23 44.93,36.57 43.38,35.02 40.98,35.02 40.61,34.65 36.26,34.65 35.03,35.88 34.41,35.88
EBI0_DQ15: length 16.8
  S3 w0.079: v2(34.17,36.08) 35.15,36.08 36.42,34.81 40.54,34.81 40.92,35.19 43.33,35.19 44.02,35.89 44.02,35.98 43.83,36.17 43.83,36.5 43.95,36.62 44.38,36.62 44.53,36.77 44.53,37 43.64,37.89 43.64,38.12 43.59,38.18 43.59,38.18 43.4,38.36 43.4,38.36 43.3,38.46 43.3,38.91 43.64,39.25 43.64,40.23 v2(43.86,40.45)
EBI0_DQS_0_M: length 5.2
  S3 w0.053: v2(34.17,38.08) 34.18,38.07 36.53,38.07 37.05,38.59 38.41,38.59 38.58,38.76 38.97,38.76 v2(39.06,38.67)
EBI0_DQS_0_P: length 5.8
  S3 w0.053: v2(39.06,39) 38.94,38.87 38.53,38.87 38.37,38.71 37,38.71 36.48,38.19 34.36,38.19 34.27,38.28 33.96,38.28 v2(33.77,38.08)
EBI0_DQS_1_M: length 15.9
  S3 w0.051: v2(33.77,35.68) 33.89,35.68 34.08,35.47 34.93,35.47 36.1,34.31 36.15,34.31 ; 44.57,38.27 44.57,38.27 44.47,38.37 44.47,38.55 44.57,38.65 v2(44.68,38.65)
  S3 w0.053: 44.57,38.27 45,38.27 45.32,37.95 45.32,36.53 43.5,34.71 41.09,34.71 40.69,34.31 36.15,34.31
EBI0_DQS_1_P: length 15.6
  S3 w0.051: v2(44.66,39) 44.56,38.88 44.56,38.81 44.35,38.6 44.35,38.32 44.52,38.15 44.57,38.15 ; 36.15,34.43 36.15,34.43 34.98,35.6 34.24,35.6 v2(34.17,35.67)
  S3 w0.053: 36.15,34.43 40.63,34.43 41.04,34.83 43.45,34.83 45.19,36.58 45.19,37.9 44.95,38.15 44.57,38.15
EBI1_CA_0: length 6.1
  S3 w0.076: 34.42,32.21 34.38,32.21 34.32,32.27 33.95,32.27 v2(33.77,32.08)
  S3 w0.079: v2(38.27,31.91) 38.18,32.01 37.48,32.01 37.2,31.73 36.48,31.73 36.1,32.11 36.1,32.21 36.23,32.33 36.23,32.4 36.2,32.43 35.85,32.43 35.8,32.38 35.8,32.28 35.72,32.21 35.63,32.21 35.57,32.27 35.57,32.35 35.51,32.41 35.42,32.41 35.36,32.35 35.36,32.27 35.3,32.21 35.22,32.21 35.16,32.27 35.16,32.35 35.1,32.41 35.01,32.41 34.95,32.35 34.95,32.27 34.89,32.21 34.42,32.21
EBI1_CA_1: length 6.2
  TOP w0.066: 35.97,32.05 35.77,32.25 35.2,32.25 34.97,32.48 SOC1.B20
  TOP w0.084: DRAM1.P2 37.94,32.33 37.01,32.33 36.73,32.05 36.61,32.05 36.54,32.11 36.54,32.32 37.05,32.83 37.05,32.92 36.97,33 36.86,33 36.39,32.52 36.04,32.52 36,32.49 36,32.4 36.2,32.2 36.2,32.1 36.15,32.05 35.97,32.05
EBI1_CA_2: length 11.7
  TOP w0.08: SOC1.A22 35.57,31.48 35.63,31.48
  TOP w0.084: v2(41.03,30.74) 41.03,30.66 40.73,30.36 40.55,30.36 40.24,30.67 40.24,30.87 40.11,31 39.53,31 39.41,30.87 39.41,30.62 39.18,30.39 38.78,30.39 38.68,30.49 38.68,30.81 38.46,31.03 38.04,31.03 37.88,30.87 37.88,30.68 37.6,30.39 37.37,30.39 36.8,30.96 36.8,31.31 36.64,31.48 35.63,31.48
  S3 w0.079: v2(41.03,30.74) 41.35,30.74 41.67,31.06 43.23,31.06 43.37,31.2 43.37,31.28 43.86,31.77 v2(43.86,32)
EBI1_CA_3: length 11.9
  TOP w0.066: 35.7,31.69 35.47,31.92 35.2,31.92 34.97,31.68 SOC1.B22
  TOP w0.084: DRAM1.R10 44.27,32.01 43.98,31.72 43.69,31.72 43.66,31.75 v2(43.47,31.75) ; v2(41.03,31.08) 40.84,31.08 40.81,31.05 40.42,31.05 40.17,31.3 40.17,31.45 39.98,31.65 39.74,31.65 39.44,31.34 39.44,31.29 39.16,31.01 38.98,31.01 38.61,31.38 38.61,31.6 38.57,31.65 38.14,31.65 37.82,31.32 37.82,31.25 37.62,31.05 37.34,31.05 36.7,31.69 35.7,31.69
  S3 w0.079: v2(41.03,31.08) 41.46,31.5 43.23,31.5 v2(43.47,31.75)
EBI1_CA_4: length 11.8
  TOP w0.084: v2(44.25,32.35) 45.12,32.35 DRAM1.R11 ; SOC1.B21 35.68,32.08 35.91,31.85 36.8,31.85 37.01,31.65 37.51,31.65 37.75,31.89 37.75,31.9 38.21,32.36 39.95,32.36 40.14,32.17 40.14,32.14 40.36,31.92 40.36,31.76 40.46,31.66 40.56,31.66 v2(41.06,31.66)
  S3 w0.079: v2(44.25,32.35) 43.71,32.35 43.51,32.16 41.56,32.16 v2(41.06,31.66)
EBI1_CA_5: length 14
  TOP w0.084: v2(44.29,31.7) 44.48,31.7 44.51,31.66 45.53,31.66 45.8,31.93 45.8,32.32 DRAM1.P11
  S3 w0.076: 34.64,31.23 v2(34.17,31.23)
  S3 w0.079: v2(44.29,31.7) 44.15,31.56 44.15,31.1 43.46,30.41 43.46,30.38 43.43,30.35 38.81,30.35 38.63,30.18 36.57,30.18 35.51,31.23 34.64,31.23
EBI1_CKE_0: length 8.1
  TOP w0.084: v2(40.39,32.21) 40.26,32.35 40.26,32.54 40.14,32.66 DRAM1.P4
  S3 w0.076: 34.42,31.62 34.39,31.65 v2(34.17,31.65)
  S3 w0.079: v2(40.39,32.21) 39.94,32.21 39.36,31.63 39.27,31.63 39.15,31.51 38.93,31.51 38.8,31.38 38.8,31.14 38.44,30.77 37.78,30.77 37.43,31.12 36.23,31.12 35.74,31.61 35.39,31.61 35.38,31.62 34.42,31.62
EBI1_CKE_1: length 8.1
  TOP w0.084: DRAM1.P5 40.74,32.66 v2(41.01,32.39)
  S3 w0.076: v2(34.17,32.06) 34.37,32.06 34.42,32.01
  S3 w0.079: 34.42,32.01 35.55,32.01 35.55,32.01 35.92,32.01 36.42,31.51 37.25,31.51 37.5,31.76 38.1,31.76 38.23,31.63 38.39,31.63 38.78,32.02 39.45,32.02 39.9,32.47 40.66,32.47 40.75,32.39 v2(41.01,32.39)
EBI1_CLK_M: length 10.3
  S3 w0.051: v2(34.17,32.48) 34.28,32.48 34.42,32.62 34.51,32.62
  S3 w0.053: v2(43.71,32.7) 43.55,32.7 43.49,32.64 43.49,32.54 43.33,32.38 42.08,32.38 41.79,32.68 39.85,32.68 39.41,32.24 36.89,32.24 36.51,32.62 34.51,32.62
EBI1_CLK_P: length 10.5
  S3 w0.051: 34.51,32.74 34.46,32.74 34.46,32.74 34.37,32.74 34.31,32.67 34.09,32.67 33.9,32.48 v2(33.77,32.48)
  S3 w0.053: v2(43.2,32.7) 43.34,32.7 43.38,32.66 43.38,32.59 43.28,32.5 42.13,32.5 41.83,32.8 39.8,32.8 39.36,32.35 36.94,32.35 36.56,32.74 34.51,32.74
EBI1_CS_0: length 7.6
  TOP w0.084: v2(39.98,31.89) 39.86,32 DRAM1.R4
  S3 w0.076: v2(33.79,31.3) 33.93,31.44 34.4,31.44 34.42,31.42
  S3 w0.079: v2(39.98,31.89) 39.88,31.79 39.8,31.79 39.33,31.31 39.33,31.21 39.33,31.13 39.17,30.97 38.95,30.97 38.94,30.96 38.94,30.96 38.31,30.34 36.7,30.34 35.61,31.42 34.42,31.42
EBI1_CS_1: length 6.5
  TOP w0.084: DRAM1.R3 v2(39.06,31.76)
  S3 w0.076: v2(33.8,31.67) 33.77,31.67 33.77,31.68 33.94,31.86 34.29,31.86 34.33,31.82 34.42,31.82
  S3 w0.079: 34.42,31.82 35.46,31.82 35.47,31.81 35.84,31.81 36.34,31.32 37.5,31.32 37.82,30.99 38.34,30.99 38.52,31.18 38.52,31.26 38.52,31.49 38.8,31.76 v2(39.06,31.76)
EBI1_DMI_0: length 6.6
  S3 w0.076: v2(33.77,30.48) 33.92,30.64 34.31,30.64
  S3 w0.079: 34.31,30.64 35.38,30.64 36.84,29.17 36.84,28.67 37.01,28.5 37.67,28.5 37.92,28.75 v2(39.06,28.75)
EBI1_DMI_1: length 17
  TOP w0.08: SOC1.A19 35.63,32.88
  TOP w0.084: DRAM1.Y10 44.32,28.76 43.99,29.08 41.82,29.08 41.76,29.14 41.76,30.2 41.7,30.25 41.54,30.25 41.48,30.31 41.48,30.38 41.54,30.44 41.7,30.44 41.76,30.49 41.76,30.57 41.7,30.62 41.54,30.62 41.48,30.68 41.48,30.75 41.54,30.81 41.7,30.81 41.76,30.86 41.76,30.94 41.7,30.99 41.54,30.99 41.48,31.04 41.48,31.12 41.54,31.17 41.7,31.17 41.76,31.23 41.76,31.3 41.7,31.36 41.54,31.36 41.48,31.41 41.48,31.49 41.54,31.54 41.7,31.54 41.76,31.59 41.76,31.67 41.7,31.73 41.54,31.73 41.48,31.78 41.48,31.86 41.54,31.91 41.7,31.91 41.76,31.96 41.76,32.04 41.7,32.09 41.54,32.09 41.48,32.15 41.48,32.22 41.54,32.28 41.7,32.28 41.76,32.33 41.76,32.41 41.7,32.46 41.54,32.46 41.48,32.51 41.48,32.59 41.54,32.64 41.7,32.64 41.76,32.7 41.76,32.77 41.7,32.83 41.67,32.83 41.62,32.88 41.62,33.44 41.46,33.6 36.89,33.6 36.17,32.88 35.63,32.88
EBI1_DQ0: length 5.8
  TOP w0.084: SOC1.A25 35.66,30.48 35.81,30.33 35.81,29.84 36.61,29.04 36.61,27.9 37.34,27.17 37.62,27.17 37.79,27.34 37.79,27.63 38.26,28.11
EBI1_DQ1: length 6.1
  TOP w0.08: 35.63,30.71 35.48,30.71 35.47,30.72 35.21,30.72 SOC1.B25
  TOP w0.084: 35.63,30.71 35.97,30.71 36.08,30.6 36.08,29.91 36.84,29.15 36.84,28.13 37.15,27.82 37.58,27.82 37.85,28.09 37.85,28.35 DRAM1.Y2
EBI1_DQ2: length 6.8
  TOP w0.08: SOC1.B24 34.97,30.88 34.97,30.88 35.32,30.88 35.32,30.88 35.63,30.88
  TOP w0.084: 35.63,30.88 36.05,30.88 36.26,30.68 36.26,30.07 37.01,29.32 37.01,28.81 37.02,28.79 37.02,28.52 37.07,28.47 37.58,28.47 37.92,28.8 37.92,28.93 38.04,29.06 38.43,29.06 38.58,29.22 38.58,29.74 DRAM1.V2
EBI1_DQ3: length 4.5
  TOP w0.08: 35.63,31.28 SOC1.A23
  TOP w0.084: 35.63,31.28 36.42,31.28 36.61,31.09 36.61,30.4 37.23,29.78 37.33,29.78 37.34,29.77 37.58,29.77 37.76,29.94 37.76,30.27 38.04,30.55 38.11,30.55 38.26,30.71
EBI1_DQ4: length 9.6
  TOP w0.084: 39.86,30.71 40.17,30.4 40.17,29.96 39.98,29.77 39.82,29.77 39.58,29.53 39.58,28.84 39.13,28.4 38.94,28.4 38.78,28.23 38.78,28.04 38.48,27.75 38.14,27.75 37.98,27.58 37.98,27.24 37.71,26.97 37.23,26.97 36.42,27.78 36.42,28.89 35.63,29.67 35.63,29.79 35.37,30.06 35.37,30.08 SOC1.A26
EBI1_DQ5: length 8.6
  TOP w0.08: 35.63,31.05 35.56,31.05 35.55,31.04 35.21,31.04 34.97,31.28 SOC1.B23
  TOP w0.084: DRAM1.V4 39.41,29.6 39.41,29.34 39.18,29.12 38.94,29.12 38.78,29.29 38.78,29.99 38.42,30.35 38.14,30.35 37.95,30.15 37.95,29.72 37.75,29.53 37.75,29.29 37.58,29.12 37.34,29.12 37.18,29.29 37.18,29.49 36.43,30.24 36.43,30.75 36.12,31.05 35.63,31.05
EBI1_DQ6: length 7.1
  S3 w0.076: 34.32,30.43 v2(34.17,30.43)
  S3 w0.079: 34.32,30.43 35.28,30.43 36.58,29.13 36.58,28.61 36.94,28.24 37.8,28.24 38.07,28.52 39.63,28.52 v2(39.86,28.75)
EBI1_DQ7: length 6.4
  S3 w0.079: v2(34.97,30.08) 35.35,30.08 36.39,29.04 36.39,28.48 36.88,27.99 37.95,27.99 38.33,28.37 39.6,28.37 v2(39.86,28.11)
EBI1_DQ8: length 17.9
  S3 w0.079: v2(34.16,33.69) 34.17,33.69 SOC1.D17 34.29,33.81 35.36,33.81 35.53,33.63 40.97,33.63 41.19,33.85 41.35,34.02 45.12,34.02 45.77,33.37 45.77,29.34 45.58,29.15 45.46,29.15 45.2,28.9 45.2,28.36 v2(45.46,28.1)
EBI1_DQ9: length 17.7
  S3 w0.079: v2(33.77,33.68) 34.07,33.99 35.46,33.99 35.67,33.78 40.88,33.78 41.12,34.02 41.12,34.02 41.28,34.18 45.18,34.18 45.93,33.42 45.93,29.22 v2(45.46,28.75)
EBI1_DQ10: length 15.1
  TOP w0.08: 35.63,33.52 35.55,33.44 35.21,33.44 SOC1.B17
  TOP w0.084: 35.63,33.52 36.24,34.13 42.37,34.13 42.68,33.82 42.68,31.32 42.94,31.06 45.6,31.06 45.8,30.86 45.8,30.14 45.71,30.06 DRAM1.V11
EBI1_DQ11: length 15.6
  TOP w0.08: 35.63,33.09 35.5,33.09 35.47,33.12 35.21,33.12 34.97,32.88 SOC1.B19
  TOP w0.084: 35.63,33.09 36.06,33.09 36.09,33.12 36.1,33.12 36.76,33.79 41.67,33.79 41.98,33.48 41.98,29.62 42.11,29.49 42.6,29.49 42.88,29.77 43.39,29.77 43.48,29.85 43.48,30.08 43.82,30.42 45.18,30.42 45.46,30.71
EBI1_DQ12: length 15.5
  TOP w0.08: SOC1.B18 35.63,33.28
  TOP w0.084: 43.86,30.71 43.61,30.71 43.32,30.42 42.5,30.42 42.21,30.71 42.21,31.13 42.26,31.18 42.46,31.18 42.51,31.24 42.51,31.31 42.46,31.37 42.26,31.37 42.21,31.42 42.21,31.5 42.26,31.55 42.46,31.55 42.51,31.61 42.51,31.68 42.46,31.73 42.26,31.73 42.21,31.79 42.21,31.86 42.26,31.92 42.46,31.92 42.51,31.97 42.51,32.05 42.46,32.1 42.26,32.1 42.21,32.16 42.21,32.23 42.26,32.29 42.46,32.29 42.51,32.34 42.51,32.42 42.46,32.47 42.26,32.47 42.21,32.52 42.21,32.6 42.26,32.65 42.46,32.65 42.51,32.71 42.51,32.78 42.46,32.84 42.26,32.84 42.21,32.89 42.21,32.97 42.26,33.02 42.46,33.02 42.51,33.08 42.51,33.15 42.46,33.21 42.26,33.21 42.21,33.26 42.21,33.77 42.01,33.96 36.55,33.96 35.87,33.28 35.63,33.28
EBI1_DQ13: length 16.7
  TOP w0.08: SOC1.A20 35.57,32.69 35.63,32.69
  TOP w0.084: 35.63,32.69 36.3,32.69 36.89,33.29 37.02,33.29 37.31,33 41.16,33 41.31,32.84 41.31,28.77 41.66,28.42 42.08,28.42 42.08,28.42 44.9,28.42 44.98,28.5 44.98,29.03 44.9,29.12 44.41,29.12 44.15,29.37 44.15,29.77 DRAM1.V9
EBI1_DQ14: length 15.4
  S3 w0.076: v2(34.17,32.87) 34.41,32.87 34.42,32.88
  S3 w0.079: v2(43.86,28.75) 43.61,29 43.61,30.35 44.37,31.11 44.37,31.42 44.54,31.59 44.54,31.81 44.51,31.84 44.51,32.46 43.63,33.34 42.8,33.34 42.41,32.96 39.69,32.96 39.29,32.55 37.04,32.55 36.65,32.94 34.48,32.94 34.42,32.88
EBI1_DQ15: length 16.8
  S3 w0.076: 34.37,33.11 34.33,33.07 33.96,33.07 v2(33.77,32.88)
  S3 w0.079: v2(43.86,28.1) 44.22,28.46 44.22,29.89 44.91,30.58 44.91,31.37 44.7,31.57 44.7,31.87 44.67,31.91 44.67,32.53 43.72,33.49 42.73,33.49 42.36,33.12 39.63,33.12 39.22,32.71 37.12,32.71 36.72,33.11 34.37,33.11
EBI1_DQS_0_M: length 6.6
  S3 w0.051: 34.45,31.02 34.43,31.04 33.96,31.04 v2(33.77,30.88)
  S3 w0.053: v2(39.06,29.9) 38.94,29.78 38.71,29.78 38.59,29.66 38.59,29.36 38.4,29.17 37.26,29.17 35.42,31.02 34.45,31.02
EBI1_DQS_0_P: length 6.2
  S3 w0.051: 34.45,30.9 34.38,30.9 34.35,30.93 34.25,30.93 v2(34.17,30.84)
  S3 w0.053: 34.45,30.9 35.37,30.9 37.21,29.06 38.45,29.06 38.71,29.31 38.71,29.61 38.76,29.66 38.97,29.66 v2(39.06,29.57)
EBI1_DQS_1_M: length 15.5
  S3 w0.051: v2(44.66,29.9) 44.77,29.79 44.84,29.79 45.18,30.13 45.18,30.13 ; 34.44,33.39 34.27,33.39 v2(34.17,33.28)
  S3 w0.053: 45.18,30.13 45.18,32.32 43.8,33.7 42.52,33.7 42.14,33.32 39.52,33.32 39.08,32.88 37.33,32.88 36.94,33.27 35.32,33.27 35.22,33.38 34.91,33.38 34.89,33.36 34.89,33.28 34.86,33.25 34.81,33.25 34.78,33.28 34.78,33.36 34.75,33.39 34.71,33.39 34.68,33.36 34.68,33.28 34.65,33.25 34.61,33.25 34.58,33.28 34.58,33.36 34.55,33.39 34.44,33.39
EBI1_DQS_1_P: length 15.9
  S3 w0.051: 34.44,33.5 34.43,33.5 34.4,33.5 34.4,33.5 33.99,33.5 v2(33.77,33.28) ; 45.3,30.13 45.3,30.08 44.89,29.67 44.77,29.67 v2(44.66,29.57)
  S3 w0.053: 45.3,30.13 45.3,32.37 43.85,33.82 42.47,33.82 42.08,33.44 39.46,33.44 39.03,33 37.39,33 36.99,33.4 35.37,33.4 35.27,33.5 34.44,33.5
EMMC1_VDDI: length 5.3
  S6 w0.3: v5(23.72,24.3) 23.72,27.97 v5(23,28.7)
  BOTTOM w0.3: C2101.1 v5(23,28.7)
FAULT_N_TP: length 5.7
  S3 w0.064: v2(37.4,9.85) 37.17,10.08 37.17,10.63 37.04,10.76 36.76,10.76 36.68,10.85 36.68,11.08 36.81,11.21 36.81,12.71 37.08,12.98 37.08,14.22 36.99,14.31 v2(36.99,14.85)
FM_ANT: length 11.5
  TOP w0.066: R2909.2 6.77,61.77 7.88,60.66 10.4,60.66 11.37,61.63 12.99,61.63 U2901.7
FORCED_USB_BOOT_N: length 99
  TOP w0.066: v2(44.07,45) JCTL1.2 43.09,45.83 47.84,45.83 48.65,46.64 48.65,53.94 50.4,55.69 v6(50.8,55.69) ; R1311.2 27.74,19.29 R1312.1 28.03,20.36 v2(28.02,20.37) 28.02,21.56 28.96,22.5 34.49,22.5 34.54,22.45 R901.2 ; v2(44.31,42.93) 44.31,42.8 43.58,42.07 21.72,42.07 20.97,41.32 20.97,37.39 22.08,36.28 22.08,33.37 21.69,32.98 21.69,29.99 v2(21.62,29.92)
  S3 w0.064: v2(26.17,29.68) 26,29.51 22.09,29.51 21.68,29.92 v2(21.62,29.92) 21.41,29.92 20.81,29.32 v3(19.45,29.32) ; v2(44.31,42.93) 44.07,43.17 v2(44.07,45) ; v2(28.02,20.37) 27.86,20.52 27.22,20.52 27.1,20.4 23,20.4 20.99,18.39 20.99,17.71 20.18,16.9 v3(19.15,16.9)
  S6 w0.064: v3(19.15,16.9) 19.6,17.35 19.6,26.7 19.08,27.22 19.08,28.95 v3(19.45,29.32)
  BOTTOM w0.066: v6(50.8,55.69) 50.86,55.75 TP2611.1
